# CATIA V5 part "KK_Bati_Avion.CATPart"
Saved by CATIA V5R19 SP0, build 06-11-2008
Part number: Bati (avion)
Bounding box of the stored display mesh (mm): x -3720 to 256, y -510 to 1598, z -447.783 to 798
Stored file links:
  G:\Khaled_CFAO_2011\ST2M\ST2M_GR2\aboulegue\Khaled\CAD_thinkMOTION\KK_Bati_Avion.CATPart
  G:\Khaled_CFAO_2011\ST2M\ST2M_GR2\aboulegue\Khaled\CAD_thinkMOTION\KK_Train_Atterrissage.CATProduct
  G:\Khaled_CFAO_2011\ST2M\ST2M_GR2\aboulegue\Khaled\CAD_thinkMOTION\KK_SqueletteBati_Avion.CATPart
  G:\Khaled_CFAO_2011\ST2M\ST2M_GR2\aboulegue\CFAO_aboulegue\CFAO_aboulegue_fichiers_catia\Douille contre fiche.CATPart
  G:\Khaled_CFAO_2011\ST2M\ST2M_GR2\aboulegue\CFAO_aboulegue\CFAO_aboulegue_fichiers_catia\Squelette_douille_contre_fiche.CATPart
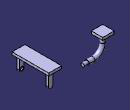
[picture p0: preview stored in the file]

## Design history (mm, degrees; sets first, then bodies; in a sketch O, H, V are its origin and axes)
Set1
  Plane1 "Plan reference": linked copy from another document
  Line1: linked copy from another document
  Line2: linked copy from another document
  Point1 "Point.23": linked copy from another document
  Line3: linked copy from another document
  Line4: linked copy from another document
  Point2 "Point.22": linked copy from another document
  Plane2 "Plan bati 1": linked copy from another document
  Line5: linked copy from another document
  Line6: linked copy from another document
  Plane3 "Plan bati 2": linked copy from another document
  Point3 "Point.11": linked copy from another document
  Point4 "Point.25": linked copy from another document
  Point5 "Point.24": linked copy from another document
  Point6 "Point.26": linked copy from another document
  Plane4 "Plan bati 3": linked copy from another document
  Line7: linked copy from another document
  Point7 "Point.18": linked copy from another document
  Line8: linked copy from another document
  Point8 "Point.27": linked copy from another document
  Plane5 "Plan bati 4": linked copy from another document
Body1 (main body)
  Sketch1 on Plane1, origin (0, 0, 0), H (0, 1, 0), V (0, 0, 1)
    line L1 (1304, 648) -> (1448, 648)
    line L2 (1448, 648) -> (1448, -160)
    line L3 (1448, -160) -> (1304, -160)
    line L4 (1304, -160) -> (1304, 648)
    reference projected line E1 (1176, 0) -> (1576, 0) from Line1
    reference projected line E2 (1376, 600) -> (1376, 0) from Line2
    reference projected point E3 (1376, 600) from Point6
    distance E1 L3 = 160
    distance E2 L4 = 72
    length L3 = 144
    distance L1 E3 = 48
    horizontal: L1 H, L3 H
    vertical: L2 V, L4 V
  Pad1: profile Sketch1, direction (1, 0, 0), length 126, mirrored extent
  Sketch2 on face of Pad1 from Sketch1.L4, origin (0, 1304, 0), H (1, 0, 0), V (0, 0, 1)
    circle A1 centre (0, 0) radius 96
    point P1 (0, 0)
    reference projected point E1 (0, 0) from Point1
    radius A1 = 96
    coincidence: E1 P1
  Pocket1: profile Sketch2, direction (0, 1, 0), length 72
  Fillet1: radius 125, on edge [face of Pad1 from Sketch1.L3 | end face of Pad1]; edge [start face of Pad1 | face of Pad1 from Sketch1.L3]
  Sketch3 on Plane1, origin (0, 0, 0), H (0, 1, 0), V (0, 0, 1)
    line L1 (-360, 648) -> (-216, 648)
    line L2 (-216, 648) -> (-216, -160)
    line L3 (-216, -160) -> (-360, -160)
    line L4 (-360, -160) -> (-360, 648)
    reference projected line E1 (-488, 0) -> (-88, 0) from Line3
    reference projected line E2 (-288, 600) -> (-288, 0) from Line4
    reference projected point E3 (-288, 600) from Point4
    distance E1 L3 = 160
    distance E2 L2 = 72
    length L3 = 144
    distance E3 L1 = 48
    horizontal: L1 H, L3 H
    vertical: L2 V, L4 V
  Pad2: profile Sketch3, direction (1, 0, 0), length 128, mirrored extent
  Sketch4 on face of Pad2 from Sketch3.L2, origin (0, -216, 0), H (-1, 0, 0), V (0, 0, 1)
    circle A1 centre (0, 0) radius 96
    point P1 (0, 0)
    reference projected point E1 (0, 0) from Point2
    radius A1 = 96
    coincidence: E1 P1
  Pocket2: profile Sketch4, direction (0, -1, 0), length 72
  Fillet2: radius 125, on edge [face of Pad2 from Sketch3.L3 | end face of Pad2]; edge [start face of Pad2 | face of Pad2 from Sketch3.L3]
  Sketch5 on Plane3, origin (0, 0, 0), H (1, 0, 0), V (0, 0, 1)
    line L1 (-421.1929, 528) -> (-389.1929, 528)
    arc A1 centre (-389.1929, 488) radius 40 from (-389.1929, 528) to (-350.2725, 497.2308) cw
    arc A2 centre (-288, 512) radius 64 from (-350.2725, 497.2308) to (-225.7275, 497.2308) ccw
    point P5 (-288, 512)
    arc A3 centre (-186.8071, 488) radius 40 from (-225.7275, 497.2308) to (-186.8071, 528) cw
    line L2 (-186.8071, 528) -> (-154.8071, 528)
    line L3 (-154.8071, 528) -> (-154.8071, 648)
    line L4 (-154.8071, 648) -> (-421.1929, 648)
    line L5 (-421.1929, 648) -> (-421.1929, 528)
    reference projected point E1 (-288, 512) from Point3
    reference projected point E2 (-288, 600) from Point5
    radius A2 = 64
    distance L2 A2 = 80
    length L1 = 32
    length L2 = 32
    radius A1 = 40
    radius A3 = 40
    distance E2 L4 = 48
    horizontal: L1 H, L2 H, L4 H
    tangency: A1 L1, A2 A1, A3 L1, A3 A2, L2 A3
    vertical: L3 V, L5 V
    coincidence: P5 E1
  Sketch6 on Plane2, origin (-288, 0, 0), H (0, 1, 0), V (0, 0, 1)
    line L1 (32, 448) -> (96, 448)
    line L2 (96, 448) -> (96, 608)
    arc A1 centre (149.5215, 608) radius 53.5215 from (96, 608) to (113.961, 648) cw
    point P4 (149.5215, 608)
    line L3 (113.961, 648) -> (13.961, 648)
    line L4 (32, 448) -> (32, 608)
    arc A2 centre (-21.3678, 608) radius 53.3678 from (32, 608) to (13.961, 648) ccw
    reference projected line E1 (-200, 512) -> (200, 512) from Line5
    reference projected line E2 (0, 600) -> (0, 512) from Line6
    reference projected point E3 (0, 600) from Point5
    length L3 = 100
    length L1 = 64
    length L2 = 160
    length L4 = 160
    distance L1 E1 = 64
    distance L4 E2 = 32
    distance E3 L3 = 48
    distance P4 L2 = 53.5215
    horizontal: L1 H, L3 H
    vertical: L2 V, L4 V
    tangency: A1 L2, A2 L4
  SolidCombine1: FirstComponentProfile Sketch5, FirstComponentDirection Sketch5, SecondComponentProfile Sketch6, SecondComponentDirection Sketch6
  Sketch7 on Plane5, origin (-2496, 0, 0), H (0, 1, 0), V (0, 0, 1)
    circle A1 centre (1056, -320) radius 128
    point P1 (1056, -320)
    reference projected point E1 (1056, -320) from Point7
    radius A1 = 128
    coincidence: E1 P1
  Sketch8 on Plane4, origin (0, 1056, 0), H (-1, 0, 0), V (0, 0, 1)
    arc A1 centre (2816, 256) radius 576 from (2816, -320) to (3392, 256) ccw
    line L1 (3392, 256) -> (3392, 648)
    point P4 (3392, 648)
    reference projected line E1 (2496, 600) -> (2496, -320) from Line8
    reference projected point E2 (2496, 600) from Point8
    line L2 (2816, -320) -> (2496, -320)
    point P5 (2496, -320)
    reference projected line E3 (2696, -320) -> (2296, -320) from Line7
    reference projected point E4 (2496, -320) from Point7
    radius A1 = 576
    distance P4 E2 = 897.2848
    length L2 = 320
    tangency: L1 A1, L2 A1
    parallelism: L1 E1
    coincidence: E3 L2, E4 P5
  Rib1: profile Sketch7, centre curve Sketch8
  Sketch9 on face of Rib1, origin (-2496, 0, 0), H (0, 1, 0), V (0, 0, 1)
    circle A1 centre (1056, -320) radius 96
    point P1 (1056, -320)
    reference projected point E1 (1056, -320) from Point7
    radius A1 = 96
    coincidence: E1 P1
  Pad3: profile Sketch9, direction (1, 0, 0), length 256
  Sketch10 on Plane1, origin (0, 0, 0), H (0, 1, 0), V (0, 0, 1)
    line L1 (-510, 798) -> (1598, 798)
    line L2 (1598, 798) -> (1598, 648)
    line L3 (1598, 648) -> (-510, 648)
    line L4 (-510, 648) -> (-510, 798)
    reference projected point E2 (0, 600) from Point5
    reference projected line E3 (-360, 648) -> (-360, -160) from edge [face of Pad2 from Sketch3.L4 | end face of Pad2]
    reference projected line E4 (1448, -160) -> (1448, 648) from edge [face of Pad1 from Sketch1.L2 | end face of Pad1]
    distance E2 L3 = 48
    length L2 = 150
    distance E3 L4 = 150
    distance L2 E4 = 150
    horizontal: L1 H, L3 H
    vertical: L2 V, L4 V
  Pad4: profile Sketch10, direction (1, 0, 0), length 256, opposite side length 480
  Sketch11 on face of Rib1, origin (0, 0, 648), H (1, 0, 0), V (0, 1, 0)
    line L1 (-3720, 1384) -> (-3064, 1384)
    line L2 (-3064, 1384) -> (-3064, 728)
    line L3 (-3064, 728) -> (-3720, 728)
    line L4 (-3720, 728) -> (-3720, 1384)
    reference projected circle E1 centre (-3392, 1056) radius 128 from edge [face of Rib1 | face of Rib1]
    reference projected circle E2 centre (-3392, 1056) radius 128 from edge [face of Rib1 | face of Rib1]
    reference projected circle E3 centre (-3392, 1056) radius 128 from edge [face of Rib1 | face of Rib1]
    reference projected circle E4 centre (-3392, 1056) radius 128 from edge [face of Rib1 | face of Rib1]
    distance L1 E1 = 200
    distance L3 E2 = 200
    distance L2 E3 = 200
    distance L4 E4 = 200
    horizontal: L1 H, L3 H
    vertical: L2 V, L4 V
  Pad5: profile Sketch11, direction (0, 0, 1), length 150
  Sketch12 on face of SolidCombine1 from Sketch6.L2, origin (0, 96, 0), H (-1, 0, 0), V (0, 0, 1)
    circle A1 centre (288, 512) radius 32
    point P1 (288, 512)
    reference projected point E1 (288, 512) from Point3
    radius A1 = 32
    coincidence: E1 P1
  Pocket3: profile Sketch12, direction (0, -1, 0), through (limit type 3)
  Sketch13 on face of SolidCombine1 from Sketch6.L2, origin (0, 96, 0), H (-1, 0, 0), V (0, 0, 1)
    circle A1 centre (288, 512) radius 48
    point P1 (288, 512)
    reference projected point E1 (288, 512) from Point3
    radius A1 = 48
    coincidence: P1 E1
  Pad6: profile Sketch13, direction (0, 1, 0), length 16
  Sketch14 on start face of Pad6, origin (0, 96, 0), H (1, 0, 0), V (0, 0, 1)
    circle A1 centre (-288, 512) radius 32
    reference projected circle E1 centre (-288, 512) radius 32 from edge [start face of Pad6 | face of Pocket3 from Sketch12.A1]
    coincidence: E1 A1
  Pad7: profile Sketch14, direction (0, -1, 0), length 144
